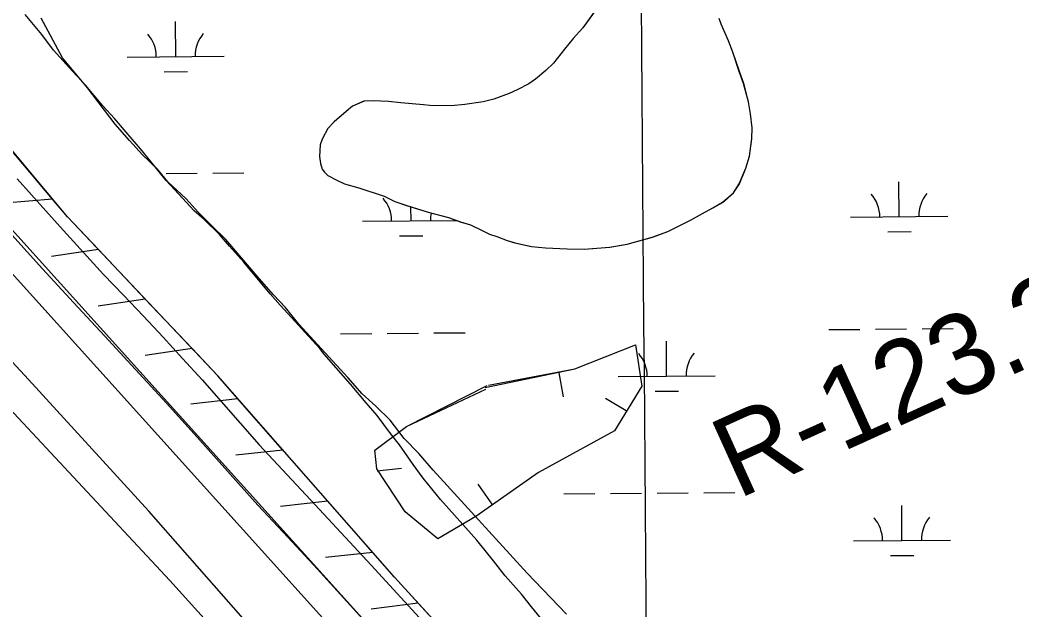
# Model space of a CAD drawing. Extents: x 3567028 to 3605064, y 510945 to 536587.
# Drawn here: x 3575751 to 3576780, y 530209 to 530815 of the extents above; entities that cross this region are included whole.
import ezdxf

# ---------------------------------------------------------------- set-up
doc = ezdxf.new("R2010")
doc.units = 0
for name, color, linetype in [('V-BORW-LINE', 7, 'Continuous'), ('V-FLOD-BASE', 7, 'Continuous'), ('V-GRID-MAJR', 7, 'Continuous'), ('V-LEVE-TOET', 7, 'Continuous'), ('V-RIVR-RANG-IDEN', 7, 'Continuous'), ('V-ROAD-CNTR', 7, 'Continuous'), ('V-RRAP-FSHR', 7, 'Continuous'), ('V-SITE-VEGE', 7, 'Continuous'), ('V-SURV-LINE', 7, 'Continuous'), ('V-WETL-SWMP', 7, 'Continuous')]:
    doc.layers.add(name, color=color, linetype=linetype)

msp = doc.modelspace()

# ---------------------------------------------------------------- linework, layer by layer
at = {"layer": 'V-BORW-LINE'}
for p, q in [((3576309.269, 530428.162), (3576304.608, 530452.723)), ((3576352.167, 530426.833), (3576373.544, 530413.87)), ((3576142.563, 530354.352), (3576117.693, 530351.81)), ((3576221.094, 530338.438), (3576235.3850000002, 530317.926))]:
    msp.add_line(p, q, dxfattribs=at)
for points in [[(3576232.078, 530440.001), (3576320.799, 530456.839), (3576383.3170000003, 530481.601), (3576389.661, 530439.1240000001), (3576361.714, 530393.036), (3576283.554, 530350.201), (3576218.916, 530305.169), (3576179.8540000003, 530282.138), (3576146.3850000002, 530309.932), (3576117.137, 530353.9130000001), (3576115.16, 530373.257), (3576147.751, 530397.684), (3576229.19, 530435.861)], [(3576228.475, 530437.653), (3576320.799, 530456.839), (3576383.3170000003, 530481.601), (3576389.661, 530439.1240000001), (3576361.714, 530393.036), (3576283.554, 530350.201), (3576218.916, 530305.169), (3576179.8540000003, 530282.138), (3576146.3850000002, 530309.932), (3576117.137, 530353.9130000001), (3576115.16, 530373.257), (3576147.751, 530397.684), (3576230.541, 530439.718)]]:
    msp.add_lwpolyline(points, dxfattribs=at)
at = {"layer": 'V-FLOD-BASE'}
msp.add_lwpolyline([(3575742.129, 530594.3910000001), (3575773.775, 530559.626), (3575805.583, 530525.011), (3575837.552, 530490.541), (3575869.366, 530456.083), (3575901.0130000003, 530421.474), (3575932.495, 530386.712), (3575963.809, 530351.797), (3575994.955, 530316.733), (3576025.632, 530283.904), (3576056.137, 530250.9130000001), (3576086.464, 530217.758), (3576116.614, 530184.4450000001)], dxfattribs=at)
at = {"layer": 'V-GRID-MAJR'}
msp.add_spline([(3576470.071, 520885.094), (3576457.305, 522452.36100000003), (3576407.9390000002, 528513.132), (3576358.572, 534573.9180000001), (3576358.556, 534575.836)], degree=3, dxfattribs=at)
at = {"layer": 'V-LEVE-TOET'}
for points in [[(3576328.22, 529817.757), (3576252.174, 529902.912), (3576130.826, 530029.866), (3576009.6210000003, 530166.41), (3575882.911, 530310.714), (3575759.083, 530445.929), (3575620.933, 530595.337), (3575533.563, 530702.73), (3575512.491, 530732.928), (3575505.051, 530748.8), (3575499.1180000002, 530764.654), (3575495.628, 530778.215), (3575494.403, 530788.711), (3575493.197, 530799.832)], [(3575747.4420000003, 530651.971), (3575791.836, 530602.767), (3575836.454, 530553.7710000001), (3575857, 530532.41), (3575877.3880000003, 530510.8960000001), (3575897.614, 530489.232), (3575917.6780000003, 530467.419), (3575937.58, 530445.458), (3575957.319, 530423.35), (3575976.894, 530401.095), (3575996.3030000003, 530378.696), (3576053.972, 530316.91), (3576111.4390000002, 530254.933), (3576168.703, 530192.77)]]:
    msp.add_lwpolyline(points, dxfattribs=at)
at = {"layer": 'V-ROAD-CNTR'}
msp.add_lwpolyline([(3576800.3233609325, 528914.9871437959), (3576753.693454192, 528991.3439910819), (3576686.9335877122, 529109.7297543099), (3576594.976771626, 529277.1294195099), (3576511.128939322, 529427.89411798), (3576441.343078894, 529554.4618648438), (3576404.169689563, 529631.6940063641), (3576356.593, 529717.454), (3576325.363, 529762.112), (3576208.201, 529901.807), (3576045.27, 530083.487), (3575904.407524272, 530239.3470651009), (3575607.0407475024, 530557.7508582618), (3575461.515038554, 530713.6945463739), (3575348.3952647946, 530831.8543100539), (3575242.5514764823, 530955.3770630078), (3575164.545632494, 531056.0308616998), (3575116.494728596, 531128.2637172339), (3575069.620822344, 531200.216573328), (3575042.5588764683, 531258.5994565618)], dxfattribs=at)
at = {"layer": 'V-RRAP-FSHR'}
for p, q in [((3575784.048393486, 530631.1257115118), (3575735.398490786, 530626.9337198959)), ((3575831.087299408, 530579.3258151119), (3575782.7833960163, 530572.1738294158)), ((3575879.2022031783, 530528.485916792), (3575830.8982997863, 530521.332931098)), ((3575927.317106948, 530477.6450184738), (3575879.013203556, 530470.493032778)), ((3575974.5660124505, 530426.0141217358), (3575926.0281095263, 530420.6761324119)), ((3576020.7429200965, 530373.4072269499), (3575972.205017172, 530368.0692376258)), ((3576066.919827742, 530320.8003321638), (3576018.3819248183, 530315.4623428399)), ((3576113.096735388, 530268.1924373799), (3576064.5588324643, 530262.854448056)), ((3576159.807641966, 530216.063541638), (3576111.38573881, 530209.7605542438))]:
    msp.add_line(p, q, dxfattribs=at)
for points in [[(3576843.396274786, 529235.0145037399), (3576767.081427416, 529394.3731850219), (3576700.5965603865, 529540.6378924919), (3576658.796643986, 529631.1337115), (3576623.522714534, 529689.1315955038), (3576582.485796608, 529737.6744984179), (3576462.513036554, 529865.1472434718), (3576302.17035724, 530060.2448532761), (3576135.514690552, 530242.6534884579), (3575953.9130537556, 530449.5430746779), (3575799.2063631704, 530613.0127477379), (3575674.889611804, 530761.5644506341), (3575618.432724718, 530850.7222723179), (3575593.960773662, 530887.4201989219)], [(3575831.087299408, 530579.3258151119), (3575799.2063631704, 530613.0127477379), (3575784.048393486, 530631.1257115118), (3575739.1244833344, 530684.8076041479)], [(3575879.2022031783, 530528.485916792), (3575831.08629941, 530579.3268151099)], [(3575927.317106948, 530477.6450184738), (3575879.2012031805, 530528.48691679)], [(3575974.5660124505, 530426.0141217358), (3575953.9130537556, 530449.5430746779), (3575927.317106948, 530477.6460184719)], [(3576020.7429200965, 530373.4072269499), (3575974.565012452, 530426.0151217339)], [(3576113.096735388, 530268.1924373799), (3576066.919827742, 530320.8003321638), (3576020.741920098, 530373.408226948)], [(3576159.807641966, 530216.063541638), (3576135.514690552, 530242.6534884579), (3576113.096735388, 530268.1934373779)], [(3576207.022547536, 530164.385644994), (3576159.807641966, 530216.064541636)]]:
    msp.add_lwpolyline(points, dxfattribs=at)
at = {"layer": 'V-SITE-VEGE'}
for p, q in [((3576392.1950000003, 530895.584), (3576329.086, 530807.324)), ((3575773.073, 530800.3749999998), (3575755.8880000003, 530821.035)), ((3576471.392, 530811.0409999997), (3576469.149, 530816.904)), ((3576478.719, 530794.0259999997), (3576471.392, 530811.0409999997)), ((3575785.078, 530784.456), (3575773.073, 530800.3749999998)), ((3576329.086, 530807.324), (3576319.014, 530796.395)), ((3576319.014, 530796.395), (3576310.107, 530785.451)), ((3576483.2090000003, 530782.301), (3576478.719, 530794.0259999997)), ((3575804.575, 530762.5949999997), (3575785.078, 530784.456)), ((3576310.107, 530785.451), (3576298.8170000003, 530771.0429999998)), ((3576489.91, 530762.376), (3576483.2090000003, 530782.301)), ((3576298.8170000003, 530771.0429999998), (3576291.127, 530763.578)), ((3575817.774, 530748.407), (3575804.575, 530762.5949999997)), ((3576291.127, 530763.578), (3576280.495, 530754.4089999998)), ((3576494.3910000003, 530750.0679999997), (3576489.91, 530762.376)), ((3575835.5330000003, 530727.1569999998), (3575817.774, 530748.407)), ((3576273.434, 530749.851), (3576261.68, 530743.612)), ((3576280.495, 530754.4089999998), (3576273.434, 530749.851)), ((3576499.359, 530731.3389999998), (3576494.3910000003, 530750.0679999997)), ((3576253.46, 530739.6539999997), (3576237.637, 530734.058)), ((3576261.68, 530743.612), (3576253.46, 530739.6539999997)), ((3575847.5810000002, 530714.152), (3575835.5330000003, 530727.1569999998)), ((3576092.364, 530726.886), (3576085.8680000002, 530721.152)), ((3576104.099, 530731.959), (3576092.364, 530726.886)), ((3576113.434, 530732.4039999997), (3576104.099, 530731.959)), ((3576129.163, 530731.587), (3576113.434, 530732.404)), ((3576141.969, 530730.2309999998), (3576129.163, 530731.5869999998)), ((3576165.257, 530728.1379999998), (3576141.969, 530730.2309999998)), ((3576171.661, 530727.462), (3576165.257, 530728.138)), ((3576193.81, 530727.1299999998), (3576171.661, 530727.4619999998)), ((3576207.822, 530728.67), (3576193.81, 530727.13)), ((3576226.5160000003, 530731.3079999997), (3576207.822, 530728.6699999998)), ((3576237.637, 530734.058), (3576226.5160000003, 530731.3079999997)), ((3576501.509, 530719.063), (3576499.359, 530731.3389999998)), ((3576085.8680000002, 530721.152), (3576073.471, 530710.8420000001)), ((3576503.041, 530704.4670000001), (3576501.509, 530719.063)), ((3575863.625, 530695.257), (3575847.5810000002, 530714.152)), ((3576073.471, 530710.8420000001), (3576066.955, 530703.9449999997)), ((3576066.955, 530703.9449999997), (3576060.9620000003, 530692.955)), ((3576502.875, 530693.3909999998), (3576503.041, 530704.4670000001)), ((3575874.514, 530682.8519999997), (3575863.625, 530695.257)), ((3576059.127, 530687.1529999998), (3576058.363, 530674.922)), ((3576060.9620000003, 530692.955), (3576059.127, 530687.1529999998)), ((3576500.2770000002, 530675.359), (3576502.875, 530693.3909999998)), ((3575884.8200000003, 530669.8740000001), (3575874.514, 530682.8519999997)), ((3576058.363, 530674.922), (3576059.424, 530667.91)), ((3576496.598, 530663.1689999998), (3576500.2770000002, 530675.359)), ((3575900.8540000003, 530650.3979999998), (3575884.8200000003, 530669.8740000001)), ((3576059.424, 530667.91), (3576061.0870000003, 530662.0569999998)), ((3576061.0870000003, 530662.0569999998), (3576063.375, 530659.108)), ((3576063.375, 530659.108), (3576066.819, 530655.559)), ((3576066.819, 530655.559), (3576076.076, 530650.7559999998)), ((3576489.944, 530646.943), (3576496.598, 530663.1689999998)), ((3575913.477, 530636.8009999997), (3575900.8540000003, 530650.3979999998)), ((3576076.076, 530650.756), (3576084.186, 530647.137)), ((3576084.186, 530647.137), (3576098.697, 530642.843)), ((3576483.977, 530637.704), (3576489.944, 530646.943)), ((3575929.538, 530619.0739999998), (3575913.477, 530636.8009999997)), ((3576098.697, 530642.843), (3576124.802, 530634.292)), ((3576124.802, 530634.292), (3576135.8000000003, 530628.881)), ((3576472.756, 530627.962), (3576483.977, 530637.704)), ((3576135.8000000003, 530628.881), (3576147.98, 530624.622)), ((3576147.98, 530624.622), (3576170.032, 530617.88)), ((3576462.759, 530622.2789999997), (3576472.756, 530627.9619999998)), ((3575939.901, 530610.177), (3575929.538, 530619.0739999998)), ((3576170.032, 530617.8799999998), (3576190.938, 530612.321)), ((3576439.838, 530609.794), (3576452.181, 530616.608)), ((3576452.181, 530616.608), (3576462.759, 530622.279)), ((3575955.412, 530594.7859999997), (3575939.901, 530610.177)), ((3576190.938, 530612.321), (3576203.1180000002, 530608.061)), ((3576203.1180000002, 530608.061), (3576213.5670000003, 530604.991)), ((3576213.5670000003, 530604.991), (3576225.72, 530598.9809999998)), ((3576416.341, 530597.899), (3576439.838, 530609.794)), ((3575965.73, 530582.973), (3575955.412, 530594.7859999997)), ((3576225.72, 530598.9809999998), (3576233.2460000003, 530595.372)), ((3576233.2460000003, 530595.372), (3576240.789, 530592.927)), ((3576240.789, 530592.9269999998), (3576251.219, 530588.6909999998)), ((3576400.518, 530592.304), (3576416.341, 530597.899)), ((3575980.644, 530566.428), (3575965.73, 530582.973)), ((3576251.219, 530588.6909999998), (3576259.344, 530586.24)), ((3576259.344, 530586.24), (3576276.1950000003, 530582.4899999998)), ((3576276.1950000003, 530582.49), (3576290.75, 530581.1100000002)), ((3576356.6380000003, 530581.88), (3576374.761, 530585.107)), ((3576374.761, 530585.107), (3576400.518, 530592.304)), ((3576290.75, 530581.11), (3576312.8910000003, 530580.1959999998)), ((3576312.8910000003, 530580.1959999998), (3576330.377, 530579.936)), ((3576330.377, 530579.936), (3576356.6380000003, 530581.88)), ((3576007.561, 530533.9649999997), (3575980.644, 530566.428)), ((3576017.88, 530522.152), (3576007.561, 530533.9649999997)), ((3576033.376, 530505.598), (3576017.88, 530522.152)), ((3576043.12, 530494.3749999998), (3576033.376, 530505.598)), ((3576058.613, 530477.823), (3576043.12, 530494.3749999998)), ((3576063.1920000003, 530471.925), (3576058.613, 530477.823)), ((3576090.136, 530441.209), (3576063.1920000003, 530471.925)), ((3576106.17, 530421.73), (3576090.136, 530441.209)), ((3576117.636, 530408.736), (3576106.17, 530421.73)), ((3576131.358, 530390.4589999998), (3576117.636, 530408.736)), ((3576140.511, 530378.6630000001), (3576131.358, 530390.4589999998)), ((3576154.787, 530358.629), (3576140.511, 530378.6630000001)), ((3576165.0700000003, 530344.486), (3576154.787, 530358.629)), ((3576182.8200000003, 530322.65), (3576165.0700000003, 530344.486)), ((3576220.092, 530280.705), (3576182.8200000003, 530322.65)), ((3576237.2660000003, 530259.4609999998), (3576220.092, 530280.705)), ((3576249.282, 530244.126), (3576237.2660000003, 530259.4609999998)), ((3576265.9080000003, 530225.225), (3576249.282, 530244.126)), ((3576276.2090000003, 530212.2439999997), (3576265.9080000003, 530225.225)), ((3576291.669, 530193.3599999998), (3576276.2090000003, 530212.2439999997))]:
    msp.add_line(p, q, dxfattribs=at)
at = {"layer": 'V-SURV-LINE'}
for points in [[(3575666.282347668, 530683.6595067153), (3576619.795368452, 529626.3128442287)], [(3576597.5266993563, 529606.2104411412), (3575644.0140916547, 530663.5566455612)]]:
    msp.add_lwpolyline(points, dxfattribs=at)
at = {"layer": 'V-WETL-SWMP'}
for p, q in [((3576392.1465622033, 530895.5763825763), (3576329.0397490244, 530807.3155692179)), ((3575794.2660265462, 530776.5814315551), (3575772.1921499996, 530817.1511364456)), ((3575910.5094043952, 530777.7006867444), (3575910.205589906, 530813.6993957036)), ((3576471.342069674, 530811.0331478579), (3576469.0980996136, 530816.8961525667)), ((3576478.668964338, 530794.0171312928), (3576471.342069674, 530811.0331478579)), ((3576329.039749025, 530807.3155692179), (3576318.9670160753, 530796.3886112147)), ((3576318.967016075, 530796.3886112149), (3576310.060256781, 530785.4436490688)), ((3576483.158904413, 530782.2911218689), (3576478.668964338, 530794.0171312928)), ((3575860.511751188, 530777.2788955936), (3575960.507057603, 530778.1224778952)), ((3576310.060256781, 530785.4436490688), (3576298.7695638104, 530771.0366973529)), ((3576489.8588236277, 530762.3691091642), (3576483.158904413, 530782.2911218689)), ((3575819.7484355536, 530745.5624958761), (3575794.2660265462, 530776.5814315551)), ((3576298.7695638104, 530771.0366973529), (3576291.079764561, 530763.5717289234)), ((3575898.640194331, 530762.1690102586), (3575922.63906787, 530762.3714700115)), ((3576291.079764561, 530763.5717289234), (3576280.4500379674, 530754.4017719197)), ((3576494.3397659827, 530750.0601000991), (3576489.8588236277, 530762.3691091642)), ((3576273.3872141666, 530749.8427996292), (3576261.6345025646, 530743.6048449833)), ((3576280.4500379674, 530754.4017719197), (3576273.3872141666, 530749.8427996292)), ((3576499.308720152, 530731.3310928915), (3576494.3397659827, 530750.0601000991)), ((3575848.404795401, 530708.1635524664), (3575819.7484355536, 530745.5624958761)), ((3576253.4147028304, 530739.6458764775), (3576237.5910811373, 530734.0509359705)), ((3576261.6345025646, 530743.6048449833), (3576253.4147028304, 530739.6458764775)), ((3576092.323396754, 530726.8804573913), (3576085.825564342, 530721.1464837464)), ((3576104.0581129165, 530731.9524127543), (3576092.323396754, 530726.8804573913)), ((3576113.391899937, 530732.3973792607), (3576104.0581129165, 530731.9524127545)), ((3576129.1205466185, 530731.5803236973), (3576113.391899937, 530732.3973792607)), ((3576141.925261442, 530730.2242788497), (3576129.1205466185, 530731.5803236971)), ((3576165.2137414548, 530728.1301970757), (3576141.925261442, 530730.2242788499)), ((3576171.6165988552, 530727.4521746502), (3576165.2137414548, 530728.1301970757)), ((3576193.7650984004, 530727.1230959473), (3576171.6165988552, 530727.4521746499)), ((3576207.7787755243, 530728.6640451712), (3576193.7650984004, 530727.1230959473)), ((3576226.4733427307, 530731.3009771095), (3576207.7787755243, 530728.6640451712)), ((3576237.5910811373, 530734.0509359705), (3576226.4733427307, 530731.3009771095)), ((3576501.458715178, 530719.0560921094), (3576499.308720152, 530731.3310928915)), ((3576085.825564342, 530721.1464837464), (3576073.4298818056, 530710.8365336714)), ((3576502.9907324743, 530704.4580948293), (3576501.4587151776, 530719.0560921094)), ((3575863.072563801, 530691.6048305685), (3575848.404795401, 530708.1635524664)), ((3576073.4298818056, 530710.8365336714), (3576066.9140539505, 530703.9375607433)), ((3576066.9140539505, 530703.9375607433), (3576060.9212288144, 530692.9495882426)), ((3576502.825775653, 530693.3841016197), (3576502.9907324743, 530704.4580948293)), ((3575876.537311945, 530676.6967909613), (3575863.072563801, 530691.6048305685)), ((3576059.0862910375, 530687.147598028), (3576058.322351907, 530674.9156076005)), ((3576060.9212288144, 530692.9495882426), (3576059.0862910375, 530687.147598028)), ((3576500.2268987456, 530675.3501209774), (3576502.825775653, 530693.3841016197)), ((3575891.8463072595, 530662.1707902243), (3575876.537311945, 530676.6967909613)), ((3576058.322351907, 530674.9156076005), (3576059.3833528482, 530667.9046077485)), ((3576496.5480254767, 530663.1621409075), (3576500.2268987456, 530675.3501209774)), ((3576059.3833528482, 530667.9046077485), (3576061.046336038, 530662.049605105)), ((3575902.4793079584, 530649.1437903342), (3575891.8463072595, 530662.1707902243)), ((3575900.679227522, 530657.5425146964), (3575932.677725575, 530657.8124610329)), ((3575948.676974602, 530657.9474342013), (3575980.6754726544, 530658.2173805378)), ((3576061.0463360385, 530662.049605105), (3576063.334294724, 530659.1005986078)), ((3576063.334294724, 530659.1005986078), (3576066.7792293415, 530655.5515883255)), ((3576066.7792293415, 530655.5515883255), (3576076.03603679, 530650.7505580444)), ((3576489.894233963, 530646.9371736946), (3576496.5480254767, 530663.1621409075)), ((3575921.213461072, 530631.5026571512), (3575902.479307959, 530649.1437903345)), ((3576076.03603679, 530650.7505580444), (3576084.143866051, 530647.1315311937)), ((3576084.143866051, 530647.1315311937), (3576098.654552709, 530642.8354819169)), ((3576483.927402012, 530637.6972001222), (3576489.894233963, 530646.9371736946)), ((3576654.2961008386, 530613.156398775), (3576653.992286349, 530649.155107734)), ((3576098.654552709, 530642.8354819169), (3576124.76099189, 530634.2863937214)), ((3576124.76099189, 530634.2863937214), (3576135.757762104, 530628.8753575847)), ((3576472.7056908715, 530627.9532455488), (3576483.927402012, 530637.6972001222)), ((3575933.6750323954, 530617.8355897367), (3575921.213461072, 530631.5026571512)), ((3576135.757762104, 530628.8753575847), (3576147.9375014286, 530624.6143165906)), ((3576147.9375014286, 530624.6143165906), (3576169.990025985, 530617.8732418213)), ((3576152.411658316, 530608.9223917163), (3576152.290454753, 530623.2836941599)), ((3576462.7109374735, 530622.2712843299), (3576472.7056908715, 530627.9532455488)), ((3575947.5607681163, 530603.7385481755), (3575933.6750323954, 530617.8355897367)), ((3576169.990025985, 530617.8732418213), (3576190.8945723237, 530612.3161704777)), ((3576439.7895010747, 530609.786372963), (3576452.133197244, 530616.5993251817)), ((3576452.133197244, 530616.5993251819), (3576462.7109374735, 530622.2712843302)), ((3576604.2984476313, 530612.7346076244), (3576704.293754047, 530613.5781899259)), ((3575962.058589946, 530589.6325201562), (3575947.5607681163, 530603.7385481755)), ((3576102.414005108, 530608.5006005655), (3576199.458825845, 530609.3192919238)), ((3576190.8945723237, 530612.3161704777), (3576203.0743116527, 530608.0541294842)), ((3576203.0743116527, 530608.0541294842), (3576213.522085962, 530604.9840939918)), ((3576213.522085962, 530604.9840939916), (3576225.676112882, 530598.9740982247)), ((3576416.2940755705, 530597.8924633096), (3576439.7895010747, 530609.7863729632)), ((3576140.542448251, 530593.3907152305), (3576164.541321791, 530593.5931749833)), ((3576225.676112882, 530598.9740982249), (3576233.200955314, 530595.3640734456)), ((3576233.200955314, 530595.3640734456), (3576240.7437931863, 530592.9200479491)), ((3576240.7437931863, 530592.9200479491), (3576251.174572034, 530588.68401317)), ((3576400.4701778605, 530592.2974793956), (3576416.2940755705, 530597.8924633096)), ((3576642.426890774, 530597.6247222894), (3576666.425764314, 530597.8271820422)), ((3575994.3900862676, 530552.1794409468), (3575962.058589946, 530589.6325201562)), ((3576251.174572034, 530588.68401317), (3576259.2993967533, 530586.2319856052)), ((3576259.2993967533, 530586.2319856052), (3576276.1500284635, 530582.4839276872)), ((3576276.1500284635, 530582.4839276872), (3576290.704703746, 530581.1018766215)), ((3576356.5922087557, 530581.8726415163), (3576374.7127868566, 530585.1005751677)), ((3576374.7127868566, 530585.1005751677), (3576400.4701778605, 530592.2974793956)), ((3576290.704703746, 530581.1018766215), (3576312.844205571, 530580.1897982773)), ((3576312.844205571, 530580.1897982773), (3576330.3298104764, 530579.9297361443)), ((3576330.3298104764, 530579.929736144), (3576356.5922087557, 530581.872641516)), ((3576011.0559732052, 530532.7304231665), (3575994.390086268, 530552.179440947)), ((3576023.3247410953, 530519.8833866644), (3576011.0559732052, 530532.7304231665)), ((3576037.1645839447, 530502.7233619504), (3576023.324741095, 530519.8833866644)), ((3576087.6212511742, 530447.8421523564), (3576037.1645839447, 530502.7233619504)), ((3576079.9812680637, 530492.8752744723), (3576111.979766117, 530493.1452208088)), ((3576127.9790151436, 530493.2801939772), (3576159.977513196, 530493.5501403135)), ((3576175.9767622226, 530493.6851134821), (3576207.975260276, 530493.9550598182)), ((3576581.8657105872, 530497.1092815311), (3576613.86420864, 530497.3792278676)), ((3576629.8634576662, 530497.514201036), (3576661.8619557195, 530497.7841473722)), ((3576677.8612047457, 530497.9191205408), (3576709.859702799, 530498.1890668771)), ((3576415.201388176, 530449.2716242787), (3576414.8975736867, 530485.270333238)), ((3576365.2037349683, 530448.849833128), (3576465.199041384, 530449.6934154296)), ((3576102.2865877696, 530431.2820480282), (3576087.6212511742, 530447.8421523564)), ((3576116.3943141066, 530418.408004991), (3576102.2865877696, 530431.2820480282)), ((3576403.332178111, 530433.7399477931), (3576427.3310516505, 530433.9424075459)), ((3576130.8890367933, 530404.0979613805), (3576116.3943141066, 530418.408004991)), ((3576145.5191633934, 530385.0879812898), (3576130.8890367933, 530404.0979613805)), ((3576160.4098800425, 530369.9549367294), (3576145.519163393, 530385.0879812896)), ((3576175.063610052, 530352.5778942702), (3576160.4098800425, 530369.9549367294)), ((3576271.7457972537, 530246.759609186), (3576175.063610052, 530352.5778942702)), ((3576309.3757171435, 530328.3036132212), (3576341.374215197, 530328.5735595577)), ((3576357.373464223, 530328.7085327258), (3576389.3719622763, 530328.9784790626)), ((3576405.371211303, 530329.1134522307), (3576437.3697093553, 530329.3833985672)), ((3576453.368958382, 530329.5183717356), (3576485.3674564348, 530329.7883180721)), ((3576657.1036420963, 530280.4933292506), (3576656.799827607, 530316.4920382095)), ((3576607.105988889, 530280.0715380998), (3576707.1012953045, 530280.9151204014)), ((3576645.234432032, 530264.9616527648), (3576669.2333055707, 530265.1641125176)), ((3576312.1766286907, 530204.6909536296), (3576271.7457972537, 530246.759609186))]:
    msp.add_line(p, q, dxfattribs=at)
for centre, radius, start, end in [((3575855.265054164, 530777.7094532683), 35.24628790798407, 359.71151968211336, 41.2551780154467), ((3575965.7457406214, 530778.641492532), 35.246287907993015, 139.7115338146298, 181.25519214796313), ((3576599.0517506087, 530613.1651652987), 35.24628790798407, 359.71151968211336, 41.2551780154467), ((3576709.532437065, 530614.0972045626), 35.246287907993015, 139.7115338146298, 181.25519214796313), ((3576097.167308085, 530608.9311582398), 35.24628790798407, 359.71151968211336, 41.2551780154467), ((3576207.6479945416, 530609.8631975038), 35.246287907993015, 168.2580380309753, 181.25519214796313), ((3576359.9570379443, 530449.2803908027), 35.24628790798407, 359.71151968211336, 41.2551780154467), ((3576470.4377244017, 530450.2124300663), 35.246287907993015, 139.7115338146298, 181.25519214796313), ((3576712.339978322, 530281.4341350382), 35.246287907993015, 139.7115338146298, 181.25519214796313), ((3576601.8592918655, 530280.5020957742), 35.24628790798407, 359.71151968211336, 41.2551780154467)]:
    msp.add_arc(centre, radius, start, end, dxfattribs=at)

# ---------------------------------------------------------------- texts
at = {"layer": 'V-RIVR-RANG-IDEN'}
msp.add_text('R-123.2', height=82.99999799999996, rotation=24.375528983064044, dxfattribs=at).set_placement((3576488.2771075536, 530322.4997715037))

doc.saveas('drawing.dxf')
